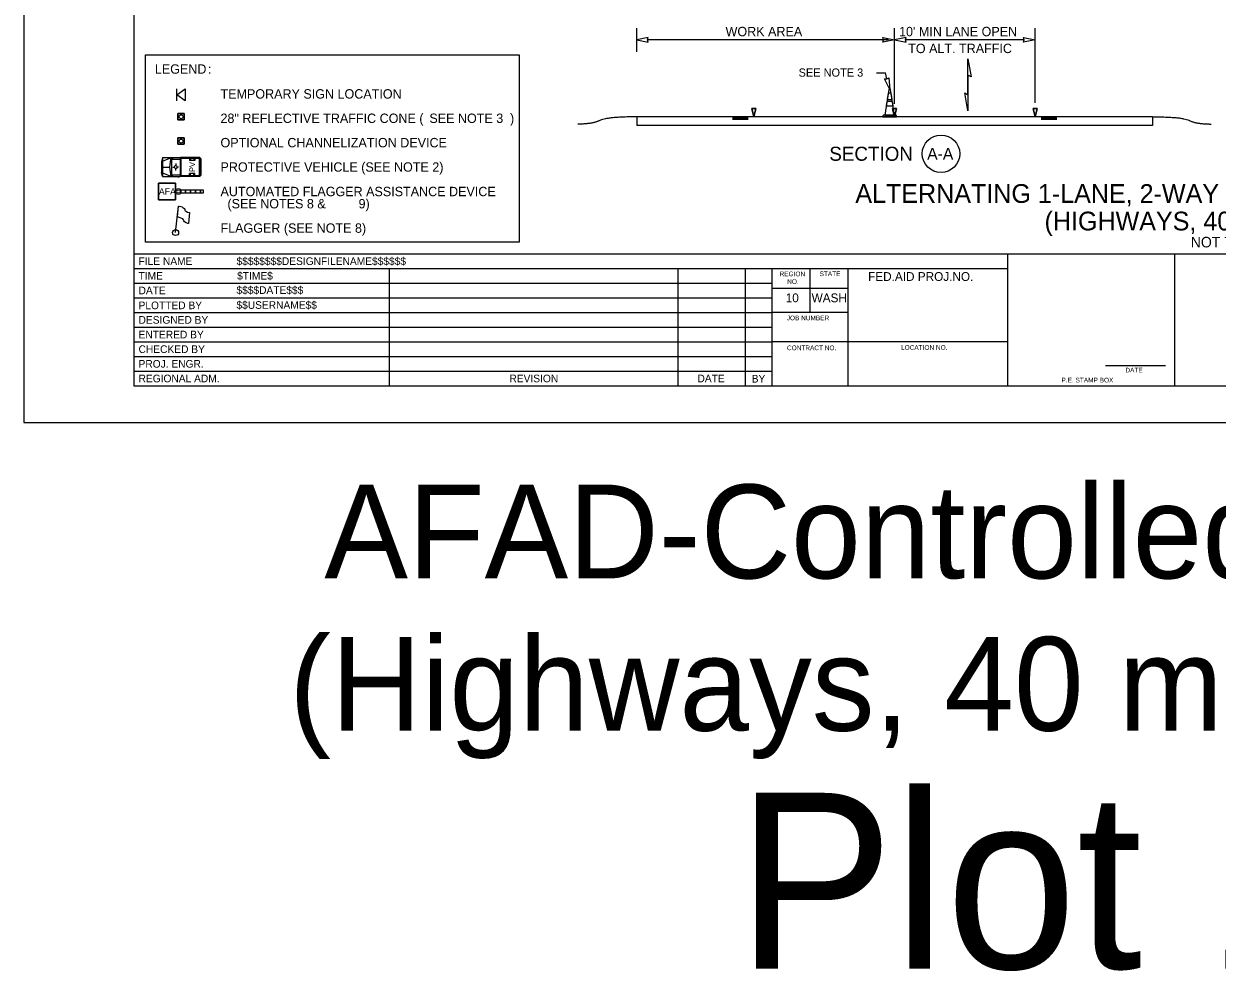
# Model space of a CAD drawing. Extents: x 99999.1 to 100095.7, y 99995 to 100010.7.
# Drawn here: x 99999.06 to 100009.24, y 99995.01 to 100003.09 of the extents above; entities that cross this region are included whole.
import ezdxf

# ---------------------------------------------------------------- set-up
doc = ezdxf.new("R2010")
doc.units = 0
for name, color, linetype in [('SH_DE_DetailHeading1Text', 7, 'Continuous'), ('SH_GI_PlotLimits', 7, 'Continuous'), ('SH_GI_SheetBorder', 7, 'Continuous'), ('SH_GI_SheetLocationText', 7, 'Continuous'), ('SH_GI_SheetTextInCells', 7, 'Continuous'), ('SH_GI_TitleBlockText', 7, 'Continuous'), ('TR_WZ_AFAD', 7, 'Continuous'), ('TR_WZ_FlaggingStation', 7, 'Continuous'), ('TR_WZ_PortableSignMountBlk-Org', 7, 'Continuous'), ('TR_WZ_ProtectiveVehicle', 7, 'Continuous'), ('TR_WZ_TrafficCone', 7, 'Continuous'), ('TR_WZ_TrafficConeElev', 7, 'Continuous'), ('TR_WZ_WorkZoneDetails', 7, 'Continuous'), ('TR_WZ_WorkZoneTextCurrent', 7, 'Continuous')]:
    doc.layers.add(name, color=color, linetype=linetype)

msp = doc.modelspace()

# ---------------------------------------------------------------- linework, layer by layer
at = {"layer": 'SH_GI_PlotLimits'}
msp.add_lwpolyline([(99999.062, 99999.687), (100016.062, 99999.687), (100016.062, 100010.687), (99999.062, 100010.687)], close=True, dxfattribs=at)
at = {"layer": 'SH_GI_SheetBorder'}
for p, q in [((100000, 100010.375), (100000, 100000)), ((100000, 100001.126), (100015.75, 100001.126)), ((100007.457, 100000), (100007.457, 100001.126)), ((100008.883, 100000), (100008.883, 100001.126)), ((100000, 100001.001), (100007.457, 100001.001)), ((100002.179, 100001.001), (100002.179, 100000)), ((100004.641, 100001.001), (100004.641, 100000)), ((100005.216, 100001.001), (100005.216, 100000)), ((100005.445, 100001.001), (100005.445, 100000)), ((100005.772, 100000.625), (100005.772, 100001.001)), ((100006.096, 100000), (100006.096, 100001.001)), ((100000, 100000.876), (100002.182, 100000.876)), ((100002.182, 100000.876), (100005.447, 100000.876)), ((100006.096, 100000.831), (100005.447, 100000.831)), ((100000, 100000.751), (100002.182, 100000.751)), ((100002.182, 100000.751), (100005.447, 100000.751)), ((100000, 100000.625), (100005.447, 100000.625)), ((100006.096, 100000.625), (100005.447, 100000.625)), ((100000, 100000.5), (100005.447, 100000.5)), ((100000, 100000.375), (100005.447, 100000.375)), ((100007.457, 100000.375), (100005.447, 100000.375)), ((100000, 100000.25), (100005.447, 100000.25)), ((100000, 100000.125), (100005.447, 100000.125)), ((100008.29, 100000.173), (100008.802, 100000.173)), ((100000, 100000), (100015.75, 100000))]:
    msp.add_line(p, q, dxfattribs=at)
at = {"layer": 'TR_WZ_AFAD'}
for p, q in [((100000.212, 100001.586), (100000.212, 100001.73)), ((100000.212, 100001.73), (100000.356, 100001.73)), ((100000.356, 100001.73), (100000.212, 100001.73)), ((100000.212, 100001.73), (100000.212, 100001.586)), ((100000.356, 100001.73), (100000.356, 100001.586)), ((100000.356, 100001.664), (100000.356, 100001.73)), ((100000.399, 100001.67), (100000.356, 100001.67)), ((100000.356, 100001.67), (100000.356, 100001.664)), ((100000.356, 100001.664), (100000.356, 100001.658)), ((100000.441, 100001.67), (100000.399, 100001.67)), ((100000.399, 100001.646), (100000.441, 100001.646)), ((100000.484, 100001.67), (100000.441, 100001.67)), ((100000.441, 100001.658), (100000.441, 100001.67)), ((100000.441, 100001.646), (100000.441, 100001.658)), ((100000.441, 100001.646), (100000.484, 100001.646)), ((100000.527, 100001.67), (100000.484, 100001.67)), ((100000.484, 100001.67), (100000.484, 100001.658)), ((100000.484, 100001.658), (100000.484, 100001.646)), ((100000.484, 100001.646), (100000.527, 100001.646)), ((100000.569, 100001.67), (100000.527, 100001.67)), ((100000.527, 100001.658), (100000.527, 100001.67)), ((100000.527, 100001.646), (100000.527, 100001.658)), ((100000.527, 100001.646), (100000.569, 100001.646)), ((100000.569, 100001.67), (100000.569, 100001.658)), ((100000.569, 100001.658), (100000.569, 100001.646)), ((100000.569, 100001.646), (100000.596, 100001.646)), ((100000.356, 100001.586), (100000.212, 100001.586)), ((100000.212, 100001.586), (100000.356, 100001.586))]:
    msp.add_line(p, q, dxfattribs=at)
for points in [[(100000.356, 100001.646), (100000.596, 100001.646), (100000.596, 100001.67), (100000.356, 100001.67)], [(100000.356, 100001.586), (100000.356, 100001.653), (100000.356, 100001.664)], [(100000.356, 100001.658), (100000.356, 100001.653), (100000.356, 100001.646), (100000.399, 100001.646)], [(100000.399, 100001.646), (100000.399, 100001.658), (100000.399, 100001.67)], [(100000.399, 100001.67), (100000.399, 100001.658), (100000.399, 100001.646)], [(100000.441, 100001.67), (100000.441, 100001.658), (100000.441, 100001.646)], [(100000.484, 100001.646), (100000.484, 100001.658), (100000.484, 100001.67)], [(100000.527, 100001.67), (100000.527, 100001.658), (100000.527, 100001.646)], [(100000.569, 100001.646), (100000.569, 100001.658), (100000.569, 100001.67)], [(100000.596, 100001.646), (100000.596, 100001.67), (100000.569, 100001.67)]]:
    msp.add_lwpolyline(points, dxfattribs=at)
at = {"layer": 'TR_WZ_FlaggingStation'}
for p, q in [((100000.357, 100001.308), (100000.383, 100001.533)), ((100000.372, 100001.441), (100000.383, 100001.533)), ((100000.372, 100001.441), (100000.372, 100001.441)), ((100000.477, 100001.479), (100000.467, 100001.385))]:
    msp.add_line(p, q, dxfattribs=at)
for points in [[(100000.383, 100001.533), (100000.387, 100001.532), (100000.402, 100001.529), (100000.413, 100001.526), (100000.42, 100001.521), (100000.427, 100001.517), (100000.432, 100001.512), (100000.435, 100001.505), (100000.436, 100001.5), (100000.44, 100001.493), (100000.449, 100001.487), (100000.458, 100001.483), (100000.477, 100001.479)], [(100000.467, 100001.385), (100000.46, 100001.386), (100000.446, 100001.39), (100000.433, 100001.398), (100000.428, 100001.407), (100000.425, 100001.415), (100000.418, 100001.424), (100000.409, 100001.429), (100000.395, 100001.434), (100000.372, 100001.441)]]:
    msp.add_lwpolyline(points, dxfattribs=at)
msp.add_circle((100000.357, 100001.308), 0.026, dxfattribs=at)
at = {"layer": 'TR_WZ_PortableSignMountBlk-Org'}
msp.add_line((100000.368, 100002.433), (100000.368, 100002.533), dxfattribs=at)
msp.add_lwpolyline([(100000.368, 100002.483), (100000.44, 100002.533), (100000.44, 100002.433)], close=True, dxfattribs=at)
at = {"layer": 'TR_WZ_ProtectiveVehicle'}
for p, q in [((100000.245, 100001.947), (100000.238, 100001.914)), ((100000.245, 100001.947), (100000.245, 100001.787)), ((100000.245, 100001.947), (100000.396, 100001.947)), ((100000.245, 100001.917), (100000.321, 100001.947)), ((100000.321, 100001.947), (100000.321, 100001.787)), ((100000.322, 100001.947), (100000.322, 100001.787)), ((100000.322, 100001.947), (100000.332, 100001.934)), ((100000.322, 100001.934), (100000.396, 100001.934)), ((100000.376, 100001.949), (100000.385, 100001.949)), ((100000.396, 100001.947), (100000.396, 100001.787)), ((100000.563, 100001.947), (100000.398, 100001.947)), ((100000.398, 100001.947), (100000.398, 100001.787)), ((100000.558, 100001.94), (100000.403, 100001.94)), ((100000.403, 100001.94), (100000.403, 100001.793)), ((100000.477, 100001.94), (100000.477, 100001.922)), ((100000.485, 100001.94), (100000.485, 100001.922)), ((100000.512, 100001.94), (100000.512, 100001.922)), ((100000.521, 100001.94), (100000.521, 100001.922)), ((100000.558, 100001.94), (100000.558, 100001.793)), ((100000.563, 100001.947), (100000.563, 100001.787)), ((100000.567, 100001.944), (100000.563, 100001.944)), ((100000.563, 100001.944), (100000.563, 100001.789)), ((100000.571, 100001.939), (100000.571, 100001.794)), ((100000.238, 100001.914), (100000.238, 100001.819)), ((100000.245, 100001.867), (100000.306, 100001.867)), ((100000.334, 100001.867), (100000.344, 100001.867)), ((100000.358, 100001.898), (100000.358, 100001.885)), ((100000.359, 100001.836), (100000.359, 100001.848)), ((100000.37, 100001.866), (100000.37, 100001.866)), ((100000.383, 100001.866), (100000.371, 100001.866)), ((100000.521, 100001.922), (100000.477, 100001.922)), ((100000.571, 100001.878), (100000.563, 100001.875)), ((100000.571, 100001.855), (100000.563, 100001.858)), ((100000.569, 100001.867), (100000.565, 100001.867)), ((100000.567, 100001.869), (100000.567, 100001.864)), ((100000.245, 100001.787), (100000.238, 100001.819)), ((100000.245, 100001.816), (100000.321, 100001.787)), ((100000.245, 100001.787), (100000.396, 100001.787)), ((100000.322, 100001.799), (100000.396, 100001.799)), ((100000.33, 100001.799), (100000.322, 100001.787)), ((100000.376, 100001.784), (100000.385, 100001.784)), ((100000.563, 100001.787), (100000.398, 100001.787)), ((100000.558, 100001.793), (100000.403, 100001.793)), ((100000.477, 100001.793), (100000.477, 100001.811)), ((100000.521, 100001.811), (100000.477, 100001.811)), ((100000.485, 100001.793), (100000.485, 100001.811)), ((100000.512, 100001.793), (100000.512, 100001.811)), ((100000.521, 100001.793), (100000.521, 100001.811)), ((100000.567, 100001.789), (100000.563, 100001.789))]:
    msp.add_line(p, q, dxfattribs=at)
for centre, major_axis, start_param, end_param in [((100000.429, 100001.867), (0, -0.168), 4.215667, 5.208926), ((100000.567, 100001.939), (0, 0.00488), 4.712389, 6.283185), ((100000.567, 100001.794), (0, -0.00488), 0, 1.570796)]:
    msp.add_ellipse(centre, major_axis=major_axis, ratio=0.73155, start_param=start_param, end_param=end_param, dxfattribs=at)
for centre, major_axis in [((100000.358, 100001.867), (0, 0.0154)), ((100000.567, 100001.867), (0, 0.00225))]:
    msp.add_ellipse(centre, major_axis=major_axis, ratio=0.73155, dxfattribs=at)
at = {"layer": 'TR_WZ_TrafficCone'}
for points in [[(100000.377, 100002.323), (100000.431, 100002.323), (100000.431, 100002.27), (100000.377, 100002.27), (100000.377, 100002.323)], [(100000.377, 100002.27), (100000.431, 100002.27), (100000.431, 100002.323), (100000.377, 100002.323), (100000.377, 100002.27)], [(100000.377, 100002.115), (100000.431, 100002.115), (100000.431, 100002.061), (100000.377, 100002.061), (100000.377, 100002.115)], [(100000.377, 100002.061), (100000.431, 100002.061), (100000.431, 100002.115), (100000.377, 100002.115), (100000.377, 100002.061)]]:
    msp.add_lwpolyline(points, dxfattribs=at)
for centre in [(100000.404, 100002.296), (100000.404, 100002.088)]:
    msp.add_circle(centre, 0.0167, dxfattribs=at)
at = {"layer": 'TR_WZ_TrafficConeElev'}
for p, q in [((100006.436, 100002.498), (100006.428, 100002.443)), ((100006.428, 100002.443), (100006.47, 100002.443)), ((100006.462, 100002.498), (100006.436, 100002.498)), ((100006.47, 100002.443), (100006.462, 100002.498)), ((100006.425, 100002.427), (100006.42, 100002.389)), ((100006.42, 100002.389), (100006.478, 100002.389)), ((100006.472, 100002.427), (100006.425, 100002.427)), ((100006.478, 100002.389), (100006.472, 100002.427)), ((100006.395, 100002.308), (100006.391, 100002.304)), ((100006.391, 100002.304), (100006.391, 100002.296)), ((100006.391, 100002.296), (100006.507, 100002.296)), ((100006.407, 100002.308), (100006.395, 100002.308)), ((100006.507, 100002.304), (100006.503, 100002.308)), ((100006.507, 100002.296), (100006.507, 100002.304))]:
    msp.add_line(p, q, dxfattribs=at)
msp.add_lwpolyline([(100006.407, 100002.308), (100006.491, 100002.308), (100006.457, 100002.529), (100006.441, 100002.529)], close=True, dxfattribs=at)
msp.add_lwpolyline([(100006.407, 100002.308), (100006.491, 100002.308), (100006.457, 100002.529), (100006.441, 100002.529)], close=True, dxfattribs=at)
msp.add_lwpolyline([(100006.503, 100002.308), (100006.491, 100002.308), (100006.407, 100002.308)], dxfattribs=at)
at = {"layer": 'TR_WZ_WorkZoneDetails'}
for p, q in [((100004.291, 100002.851), (100004.291, 100003.051)), ((100006.491, 100002.405), (100006.491, 100003.051)), ((100007.691, 100002.415), (100007.691, 100003.051)), ((100006.439, 100002.951), (100004.384, 100002.951)), ((100007.597, 100002.951), (100006.584, 100002.951)), ((100006.336, 100002.672), (100006.412, 100002.672)), ((100006.425, 100002.62), (100006.412, 100002.672)), ((100007.116, 100002.652), (100007.116, 100002.483)), ((100007.116, 100002.483), (100007.116, 100002.652)), ((100004.291, 100002.295), (100004.291, 100002.22)), ((100008.691, 100002.295), (100004.291, 100002.295)), ((100005.108, 100002.29), (100005.241, 100002.29)), ((100005.108, 100002.285), (100005.241, 100002.285)), ((100005.108, 100002.279), (100005.241, 100002.279)), ((100005.108, 100002.274), (100005.241, 100002.274)), ((100007.874, 100002.29), (100007.741, 100002.29)), ((100007.874, 100002.284), (100007.741, 100002.284)), ((100007.874, 100002.278), (100007.741, 100002.278)), ((100007.874, 100002.273), (100007.741, 100002.273)), ((100008.691, 100002.295), (100008.691, 100002.22)), ((100008.691, 100002.22), (100004.291, 100002.22))]:
    msp.add_line(p, q, dxfattribs=at)
for points in [[(100004.291, 100002.951), (100004.389, 100002.932), (100004.384, 100002.951), (100004.389, 100002.971)], [(100006.491, 100002.951), (100006.392, 100002.932), (100006.397, 100002.951), (100006.392, 100002.971)], [(100006.491, 100002.951), (100006.589, 100002.932), (100006.584, 100002.951), (100006.589, 100002.971)], [(100007.691, 100002.951), (100007.592, 100002.932), (100007.597, 100002.951), (100007.592, 100002.971)], [(100007.116, 100002.789), (100007.143, 100002.636), (100007.116, 100002.652)], [(100006.449, 100002.529), (100006.406, 100002.619), (100006.426, 100002.62), (100006.443, 100002.629)], [(100007.116, 100002.345), (100007.089, 100002.499), (100007.116, 100002.483)], [(100005.291, 100002.295), (100005.274, 100002.365), (100005.307, 100002.365)], [(100006.491, 100002.295), (100006.474, 100002.365), (100006.507, 100002.365)], [(100007.691, 100002.295), (100007.674, 100002.365), (100007.707, 100002.365)]]:
    msp.add_lwpolyline(points, close=True, dxfattribs=at)
for points in [[(100005.307, 100002.365), (100005.274, 100002.365), (100005.291, 100002.295), (100005.307, 100002.365)], [(100006.507, 100002.365), (100006.474, 100002.365), (100006.491, 100002.295), (100006.507, 100002.365)], [(100007.707, 100002.365), (100007.674, 100002.365), (100007.691, 100002.295), (100007.707, 100002.365)]]:
    msp.add_lwpolyline(points, dxfattribs=at)
msp.add_circle((100006.887, 100001.98), 0.16, dxfattribs=at)
for points in [[(100004.291, 100002.295), (100004.04, 100002.295), (100003.914, 100002.233), (100003.789, 100002.233)], [(100008.691, 100002.295), (100008.942, 100002.296), (100009.067, 100002.233), (100009.193, 100002.234)]]:
    msp.add_open_spline(points, degree=2, dxfattribs=at)
at = {"layer": 'TR_WZ_WorkZoneTextCurrent'}
msp.add_lwpolyline([(100000.1, 100002.823), (100003.289, 100002.823), (100003.289, 100001.226), (100000.1, 100001.226)], close=True, dxfattribs=at)

# ---------------------------------------------------------------- texts
at = {"layer": 'SH_DE_DetailHeading1Text'}
for s, height, p in [('ALTERNATING 1-LANE, 2-WAY TRAFFIC: AFAD-CONTROLLED', 0.16, (100006.156, 100001.561)), ('(HIGHWAYS, 40 MPH OR LESS)', 0.16, (100007.77, 100001.326)), ('NOT TO SCALE', 0.09, (100009.017, 100001.181))]:
    msp.add_text(s, height=height, rotation=360, dxfattribs=at).set_placement(p)
at = {"layer": 'SH_GI_SheetLocationText'}
for s, height, p in [('AFAD-Controlled Alt Traffic', 0.8, (100001.626, 99998.357)), ('(Highways, 40 mph or Less)', 0.8, (100001.326, 99997.057)), ('Plot 1', 1.5, (100005.145, 99995.027))]:
    msp.add_text(s, height=height, dxfattribs=at).set_placement(p)
at = {"layer": 'SH_GI_SheetTextInCells'}
for s, height, p in [('FILE NAME', 0.0651, (100000.041, 100001.031)), ('TIME', 0.0651, (100000.041, 100000.906)), ('REGION', 0.04, (100005.51, 100000.935)), ('STATE', 0.04, (100005.851, 100000.936)), ('FED.AID PROJ.NO.', 0.07506, (100006.265, 100000.895)), ('DATE', 0.0651, (100000.041, 100000.781)), ('NO.', 0.04, (100005.575, 100000.869)), ('PLOTTED BY', 0.0651, (100000.041, 100000.654)), ('10', 0.0751, (100005.562, 100000.713)), ('WASH', 0.0751, (100005.783, 100000.713)), ('DESIGNED BY', 0.06505, (100000.041, 100000.53)), ('JOB NUMBER', 0.04, (100005.571, 100000.559)), ('ENTERED BY', 0.0651, (100000.041, 100000.405)), ('CHECKED BY', 0.0651, (100000.041, 100000.28)), ('CONTRACT NO.', 0.04003, (100005.573, 100000.304)), ('LOCATION NO.', 0.04003, (100006.546, 100000.307)), ('PROJ. ENGR.', 0.06505, (100000.041, 100000.155)), ('DATE', 0.04, (100008.46, 100000.114)), ('REGIONAL ADM.', 0.06505, (100000.041, 100000.03)), ('REVISION', 0.0651, (100003.205, 100000.03)), ('DATE', 0.0651, (100004.809, 100000.03)), ('BY', 0.0651, (100005.272, 100000.028)), ('P.E. STAMP BOX', 0.04003, (100007.915, 100000.029))]:
    msp.add_text(s, height=height, dxfattribs=at).set_placement(p)
at = {"layer": 'SH_GI_TitleBlockText'}
for s, height, p in [('$$$$$$$$DESIGNFILENAME$$$$$$', 0.06505, (100000.877, 100001.031)), ('$TIME$', 0.0651, (100000.882, 100000.906)), ('$$$$DATE$$$', 0.06505, (100000.876, 100000.784)), ('$$USERNAME$$', 0.06505, (100000.876, 100000.657))]:
    msp.add_text(s, height=height, dxfattribs=at).set_placement(p)
at = {"layer": 'TR_WZ_AFAD'}
msp.add_text('AFAD', height=0.056, dxfattribs=at).set_placement((100000.214, 100001.63))
at = {"layer": 'TR_WZ_ProtectiveVehicle'}
msp.add_text('PV', height=0.048, rotation=90, dxfattribs=at).set_placement((100000.523, 100001.824))
at = {"layer": 'TR_WZ_WorkZoneDetails'}
for s, p in [('WORK AREA', (100005.049, 100002.983)), ("10' MIN LANE OPEN", (100006.529, 100002.983)), ('TO ALT. TRAFFIC', (100006.607, 100002.839))]:
    msp.add_text(s, height=0.08, dxfattribs=at).set_placement(p)
for s, height, p in [('SECTION', 0.12, (100005.934, 100001.92)), ('A-A', 0.1, (100006.769, 100001.93))]:
    msp.add_text(s, height=height, rotation=360, dxfattribs=at).set_placement(p)
at = {"layer": 'TR_WZ_WorkZoneTextCurrent'}
for s, p in [('LEGEND', (100000.18, 100002.663)), (':', (100000.633, 100002.663)), ('TEMPORARY SIGN LOCATION ', (100000.74, 100002.451)), ('28" REFLECTIVE TRAFFIC CONE (', (100000.74, 100002.243)), ('SEE NOTE 3', (100002.522, 100002.243)), (')', (100003.21, 100002.243)), ('OPTIONAL CHANNELIZATION DEVICE', (100000.74, 100002.035)), ('PROTECTIVE VEHICLE (SEE NOTE 2)', (100000.74, 100001.827)), ('AUTOMATED FLAGGER ASSISTANCE DEVICE', (100000.74, 100001.618)), ('  (SEE NOTES 8 &', (100000.74, 100001.514)), ('9)', (100001.918, 100001.514)), ('FLAGGER (SEE NOTE 8)', (100000.74, 100001.306))]:
    msp.add_text(s, height=0.08, rotation=360, dxfattribs=at).set_placement(p)
msp.add_text('SEE NOTE 3', height=0.07, dxfattribs=at).set_placement((100005.672, 100002.638))

doc.saveas('drawing.dxf')
